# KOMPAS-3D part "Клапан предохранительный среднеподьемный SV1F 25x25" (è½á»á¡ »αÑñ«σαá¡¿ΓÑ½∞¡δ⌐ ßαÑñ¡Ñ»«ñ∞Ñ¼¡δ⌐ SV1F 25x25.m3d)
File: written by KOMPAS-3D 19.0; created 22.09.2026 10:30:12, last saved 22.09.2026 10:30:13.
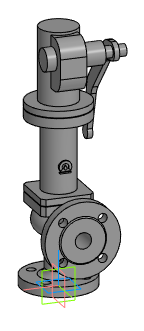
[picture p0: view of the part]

Document properties: Автор: Евгений; Полное имя файла: Z:\3.Личные\sachek\Dendor\_3D для проектировщиков\5.8 SV1F. Клапан предохранительный среднеподьемный\SV1F_STP\Клапан предохранительный среднеподьемный SV1F 25x25.m3d

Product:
- Part/product: Клапан предохранительный среднеподьемный SV1F 25x25
    Масса: 15.572

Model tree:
1. Операция без истории:1  (labels: Клапан предохранительный среднеподьемный SV1F 25x25)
